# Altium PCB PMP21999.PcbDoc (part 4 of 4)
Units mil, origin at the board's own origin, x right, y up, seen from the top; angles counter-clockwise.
Board outline 7450 x 5800 mil, 6 copper layers (Top Layer, Signal Layer 3, Signal Layer 1, Signal Layer 2, Signal Layer 4, Bottom Layer), stack 66 mil thick; 237 components, 96 nets, 712 pads, 268 vias.
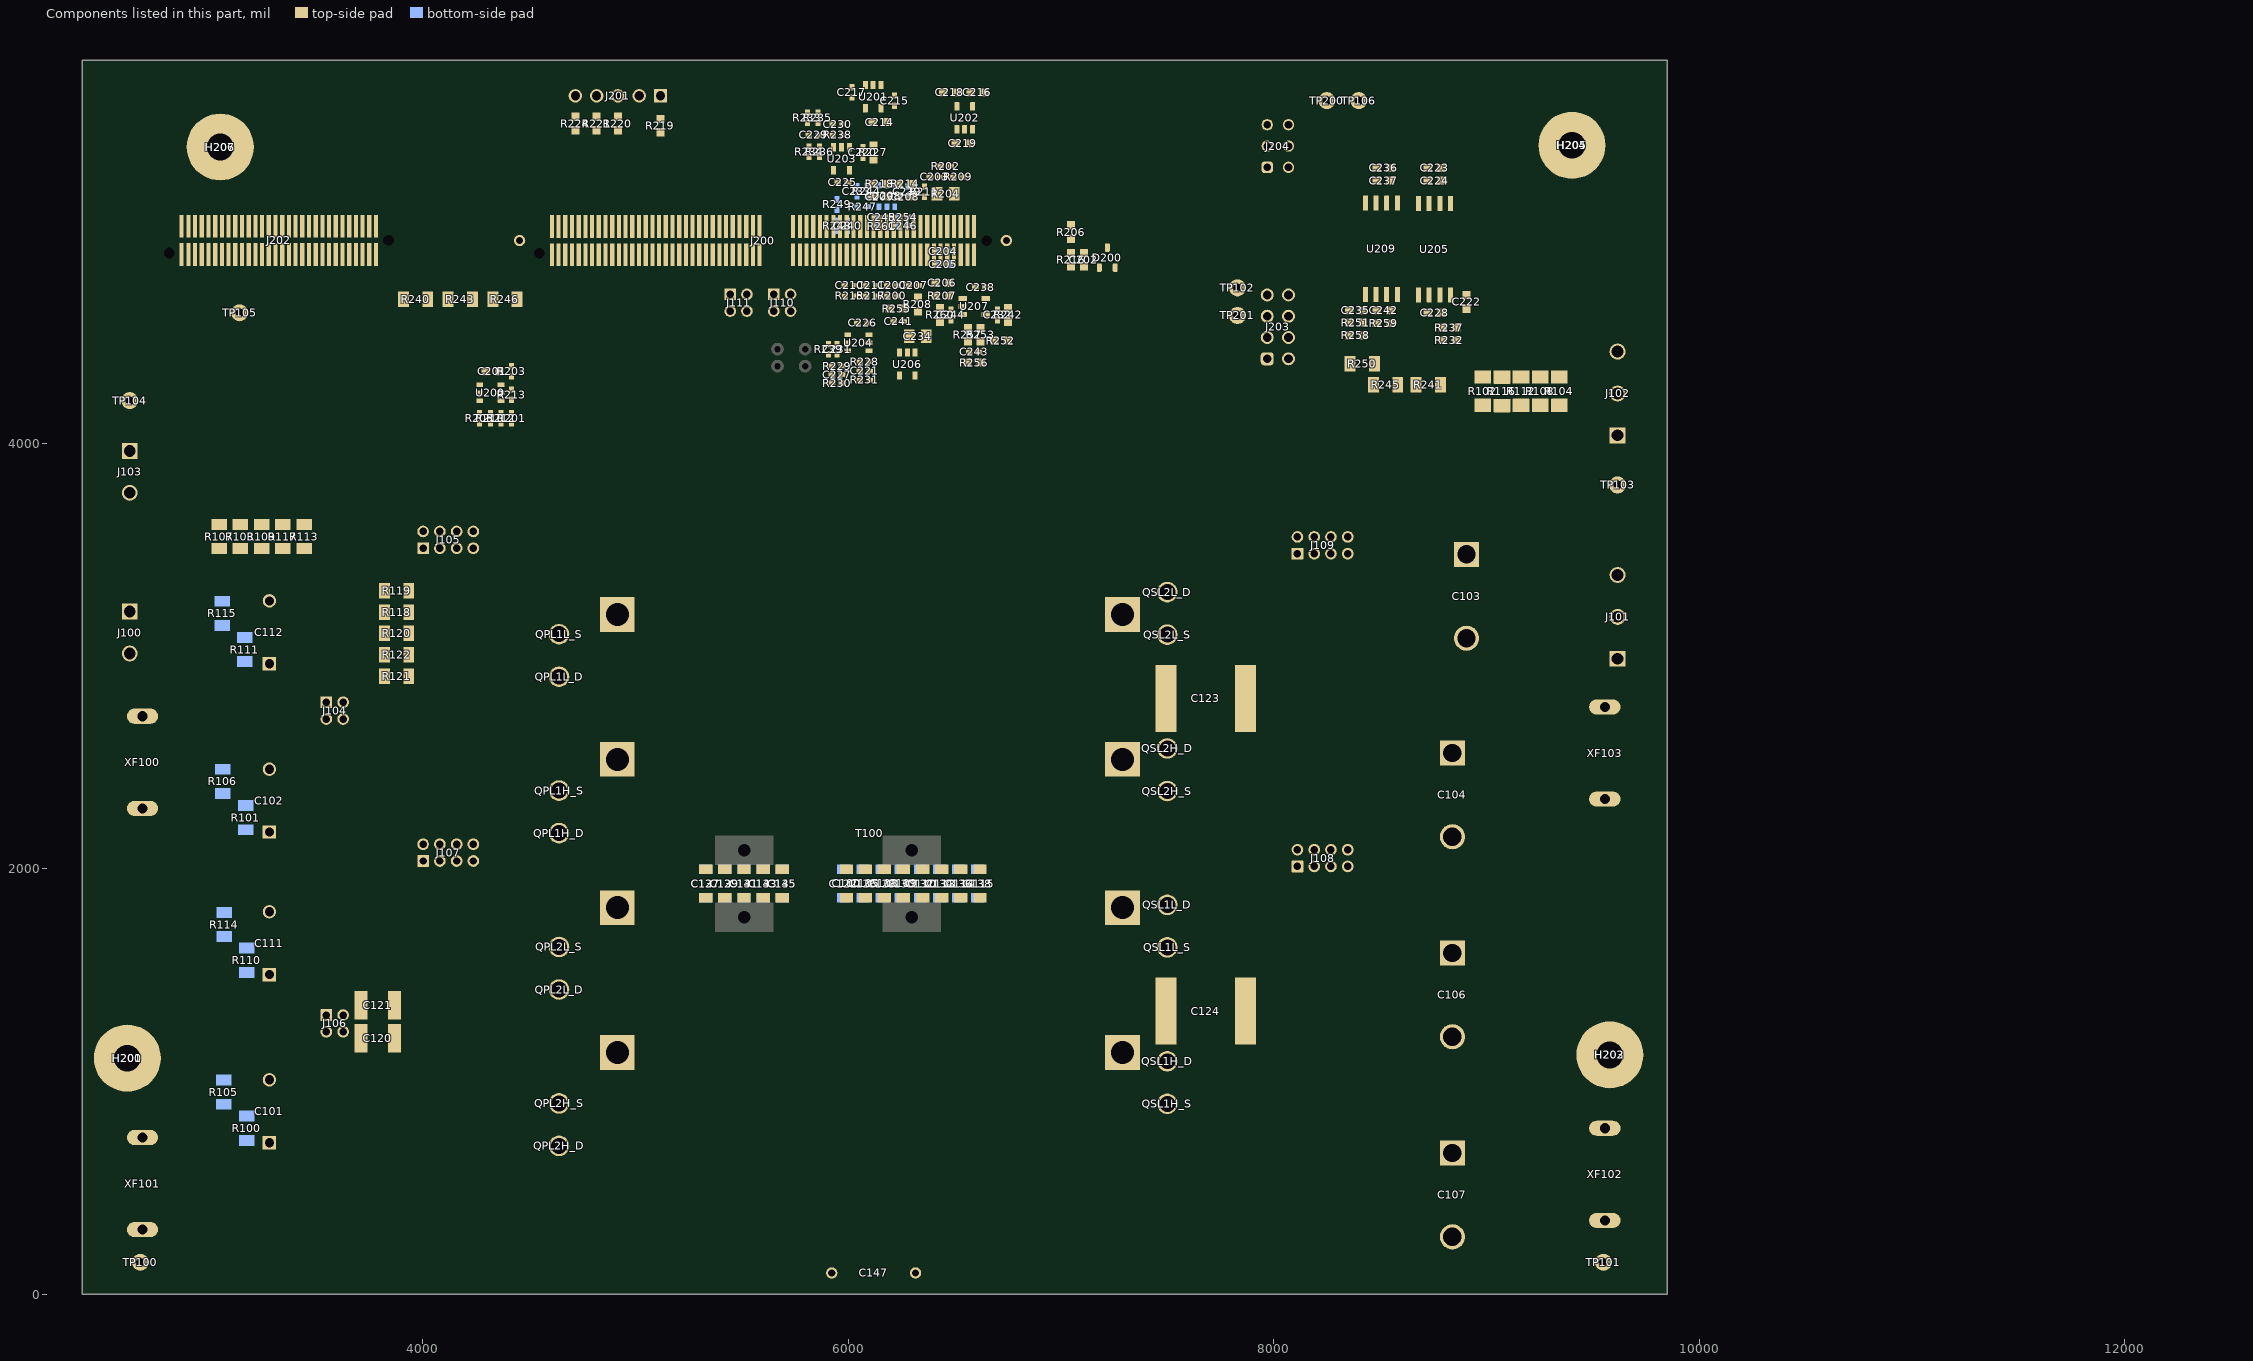
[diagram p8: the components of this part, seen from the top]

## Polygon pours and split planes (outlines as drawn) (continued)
VBUS on Signal Layer 4 "VBUS" (solid, pour order 274): 2510,3270 2490,3250 2490,2240 2510,2220 2840,2220 2860,2240 2860,3250 2840,3270
BATT_RTN on Signal Layer 4 "BATT_RTN" (solid, pour order 430): 8929.94,4280 8916.4,4293.54 8916.4,4453.54 9026.4,4563.54 9786.4,4563.54 9806.4,4543.54 9806.4,3926.4 9640,3760 9590,3760 9426.4,3923.6 9426.4,4223.54 9369.94,4280
VBATT on Signal Layer 4 "VBATT" (solid, pour order 442): 9636.4,2233.54 9686.4,2283.54 9686.4,3443.54 9656.4,3473.54 9536.4,3473.54 9376.4,3313.54 9376.4,2283.54 9426.4,2233.54
SGND on Signal Layer 4 "SGND" (solid, pour order 478): 39 vertices, not listed, extent 7438.19,1340 8480,4160
HVBUS on Signal Layer 4 "HVBUS" (solid, pour order 496): 36 vertices, not listed, extent 2580,80 4700,2240
SGND on Signal Layer 4 "SGND" (solid, pour order 518): 33 vertices, not listed, extent 6290,10 9410,4210
RTN on Signal Layer 4 "RTN" (solid, pour order 522): 2580,4260 2560,4240 2560,3740 2702.64,3597.36 3476.26,3597.36 3497.49,3618.59 3497.49,4039.53 3277.02,4260
PGND on Signal Layer 4 "PGND" (solid, pour order 532): 27 vertices, not listed, extent 2560,3381.39 9830,5791
SGND on Signal Layer 4 "SGND" (solid, pour order 542): 19 vertices, not listed, extent 7670,4169.11 9030,4807.01
no net on Bottom Layer "LEG_2_SEC" (solid, pour order 416): 17 vertices, not listed, extent 7100,2300 7560,3390
Leg_2_Sec on Bottom Layer "LEG_2_SEC" (solid, pour order 410): 17 vertices, not listed, extent 7100,2300 7560,3390
Leg_1_Sec on Bottom Layer "LEG_1_SEC" (solid, pour order 398): 17 vertices, not listed, extent 7100,780 7560,1930
VOUT on Bottom Layer "Vout" (solid, pour order 392): 35 vertices, not listed, extent 7440,100 9680,3570
PGND on Bottom Layer "PGND" (solid, pour order 390): 20 vertices, not listed, extent 2920,1100 3840,3530
Crs_1 on Bottom Layer "Crs_1" (solid, pour order 356): 5951.81,1890 5931.81,1870 5931.81,1730 5951.81,1710 6661.81,1710 6681.81,1730 6681.81,1870 6661.81,1890
NetC100_2 on Bottom Layer "C100_2" (solid, pour order 342): 5950,2150.16 5930,2130.16 5930,1980 5950.39,1959.61 6659.61,1959.61 6680,1980 6680,2130 6660,2150
NetC102_2 on Bottom Layer "C102_2" (solid, pour order 332): 2983.46,2463.86 2983.46,2883.86 3103.46,3003.86 3323.46,3003.86 3343.46,2983.86 3343.46,2443.86 3323.46,2423.86 3253.46,2423.86 3233.46,2443.86 3003.46,2443.86
NetC101_2 on Bottom Layer "C101_2" (solid, pour order 318): 2970,1000 2970,1420 3090,1540 3310,1540 3330,1520 3330,980 3310,960 3240,960 3220,980 2990,980
HVBUS on Bottom Layer "HVBUS" (solid, pour order 284): 34 vertices, not listed, extent 2580,80 4700,2240
Leg_1_Prim on Bottom Layer "Leg_1_Prim" (solid, pour order 300): 4840,3300 4820,3280 4820,3101.26 4678.74,2960 4600,2960 4580,2940 4580,2330 4600,2310 4890,2310 5010,2430 5010,3280 4990,3300
Leg_2_Prim on Bottom Layer "Leg_2_Prim" (solid, pour order 296): 4613.42,1480 4593.42,1460 4593.42,860 4613.42,840 4813.42,840 5023.42,1050 5023.42,1220 4763.42,1480
NetC127_1 on Bottom Layer "BOTTOM_LAYER_NETC127_1_P254" (solid, remove dead copper, pour order 254): 5180,1940 5150,1970 5150,2139.44 5170.56,2160 5850,2160 5870,2140 5870,1970 5840,1940
Crp_1 on Bottom Layer "BOTTOM_LAYER_CRP_1_P260" (solid, remove dead copper, pour order 260): 5180,1890 5150,1860 5150,1730 5180,1700 5830,1700 5860,1730 5860,1870 5840,1890
VBUS on Bottom Layer "VBUS" (solid, pour order 272): 2510,3270 2490,3250 2490,2240 2510,2220 2840,2220 2860,2240 2860,3250 2840,3270
BATT_RTN on Bottom Layer "BATT_RTN" (solid, pour order 432): 8929.94,4280 8916.4,4293.54 8916.4,4453.54 9026.4,4563.54 9786.4,4563.54 9806.4,4543.54 9806.4,3926.4 9640,3760 9590,3760 9426.4,3923.6 9426.4,4223.54 9369.94,4280
VBATT on Bottom Layer "VBATT" (solid, pour order 450): 9636.4,2233.54 9686.4,2283.54 9686.4,3443.54 9656.4,3473.54 9536.4,3473.54 9376.4,3313.54 9376.4,2283.54 9426.4,2233.54
SGND on Bottom Layer "SGND" (solid, pour order 482): 21 vertices, not listed, extent 7660,1110 9410,4210
SGND on Bottom Layer "SGND" (solid, pour order 480): 28 vertices, not listed, extent 7440,3031.26 8480,4160
no net on Bottom Layer "HVBUS" (solid, pour order 490): 34 vertices, not listed, extent 2580,80 4700,2240
CS on Bottom Layer "CS" (solid, pour order 506): 17 vertices, not listed, extent 3900,1570 4710,3390
RTN on Bottom Layer "RTN" (solid, pour order 520): 2580,4260 2560,4240 2560,3740 2700,3600 3479.74,3600 3497.49,3617.75 3497.49,4039.53 3277.02,4260
PGND on Bottom Layer "PGND" (solid, pour order 530): 33 vertices, not listed, extent 2560,3360 9830,5791
SGND on Bottom Layer "SGND" (solid, pour order 540): 23 vertices, not listed, extent 7670,4141.13 9030,4807.01

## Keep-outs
Keep-Out Layer:
  text ".Layer_Name" at 577,-858.49 h60

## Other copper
Top Layer:
  text ".Layer_Name" at 577,-858.49 h60
Bottom Layer:
  text ".Layer_Name" at 577,-858.49 h60

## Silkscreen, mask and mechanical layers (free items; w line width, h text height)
Top Overlay:
  drawing of 153 lines, arcs and shapes, not listed
  text "5Vp" at 8170,5480 h72.83
  text "PGND" at 8370,5480 h72.83
  text "V1: 400V-600V DC / Power Max 7kW" at 2440,5115.5 h100 r270
  text "SGND" at 7616.01,4780 h72.83
  text "V2 / 250-450V DC / Pmax 6.6kW" at 9710,4670 h100 r90
  text "5Vs" at 7660,4627.86 h72.83
  text "-" at 9716.4,4623.54 h150
  text "Coil_Sec_N" at 4818,4550 h60
  text "Coil_Pri_N" at 4820,4450 h60
  text "PMP21999 RevA" at 2743.46,4394.47 h108.27
  text "Coil_Pri_P" at 4820,4350 h60
  text "Coil_Sec_P" at 4818,4231.87 h60
  text "-" at 2477.8,4109.68 h150
  text "+" at 9726.4,3513.58 h150
  text "+" at 2463.46,3330 h150
  text "Fuse F30AL650V / Installed between XF100 & XF101" at 2454.17,2172.36 h100 r270
  text "Crp" at 5170,2100 h30
  text "Crs" at 6008.16,2090 h30
  text "Board" at 5170,2040 h30
  text "Board" at 6008.79,2036.18 h30
  text "Fuse F30AL650V / Installed between XF102 & XF103" at 9808.81,1430 h100 r90
  text ".Layer_Name" at 577,-858.49 h60
  text "Fuse F30AL650V / Installed between XF100 & XF101" at 3950,-2600 h100 r270
  text "Fuse F30AL650V / Installed between XF100 & XF101" at -5650,-2780 h100 r270
Bottom Overlay:
  lines w10: 6338,5181.87 6378,5221.87 6718,5221.87 ; 6718,5111.87 6718,5431.87 6748,5461.87 7178,5461.87 7218,5421.87 7218,5121.87 7178,5081.87 6748,5081.87 6718,5111.87
  text ".Layer_Name" at 577,-858.49 h60
Top Paste:
  text ".Layer_Name" at 577,-858.49 h60
Bottom Paste:
  text ".Layer_Name" at 577,-858.49 h60
Top Solder:
  text ".Layer_Name" at 577,-858.49 h60
  text ".Layer_Name" at 577,-858.49 h60
Bottom Solder:
  text ".Layer_Name" at 577,-858.49 h60
Drill Guide:
  text ".Layer_Name" at 577,-858.49 h60
M1 Board Outline:
  the board outline again, w10
  text ".Layer_Name" at 577,-858.49 h60
M2 Board Dimensions:
  rectangle: 0,-275 125,-150
  rectangle: 125,-400 500,-275
  lines w7: 0,-275 1000,-275 ; 125,-400 125,-150 ; 250,-400 250,-150 ; 500,-400 500,-150 ; 750,-400 750,-150 ; 0,-400 1000,-400 1000,-150 0,-150 0,-400
  text ".Layer_Name" at 577,-858.49 h60
M3 3D STEP Top:
  text ".Layer_Name" at 577,-858.49 h60
M4 3D STEP Bottom:
  text ".Layer_Name" at 577,-858.49 h60
M5 Assembly Top:
  lines w10: -292,-930.17 6308,-930.17 ; -292,-726.83 6310,-726.83 ; -292,-523.5 -292,-1133.5 3713,-1133.5 6310,-1133.5 6310,-523.5 -291.5,-523.5 -291.5,-1133.5 1284,-1133.5 ; 2173,-1133.5 2173,-523.5 ; 3440,-726.83 3440,-523.5 ; 4280,-726.83 4280,-523.5 ; 4902,-1140 4902,-937.17
  text "COMPONENTS MARKED 'DNP' SHOULD NOT BE POPULATED." at 1153.5,-318.5 h60
  text "ASSEMBLY VARIANT:" at 1153,-434 h60
  text ".VariantName" at 2189,-434 h60
  text "PCB VIEWED FROM TOP SIDE" at -228.5,-655.67 h60
  text "BOARD #:" at 2248,-655.67 h60
  text ".PRJ_Number" at 2793.5,-655.67 h60
  text "REV:" at 3638,-655.67 h60
  text ".PCB_Rev" at 3929.5,-655.67 h60
  text "SVN REV:" at 4476,-655.67 h60
  text ".VersionControl_RevNumber" at 4982,-655.67 h60
  text "TID #:" at 2248,-859 h60
  text ".TID" at 2793.5,-859 h60
  text "PLOT NAME =" at -228.5,-1064.34 h60
  text ".plot_File_Name" at 577,-1064.34 h60
  text "GENERATED    :" at 2250,-1064.34 h60
  text ".Print_Date" at 3119.5,-1064.34 h60
  text ".Print_Time" at 3848.5,-1064.34 h60
  text "TEXAS INSTRUMENTS" at 5113,-1064.34 h60
M6 Assembly Bottom:
  lines w10: -292.5,-727.33 6309.5,-727.33 ; -290.5,-930.67 6309.5,-930.67 ; 1115.5,-1140.5 1115.5,-937.67 ; 1737.5,-727.33 1737.5,-524 ; 2577.5,-727.33 2577.5,-524 ; 3844.5,-1134 3844.5,-524 ; 4733.5,-1134 6309,-1134 6309,-524 -292.5,-524 -292.5,-1134 2304.5,-1134 6309.5,-1134 6309.5,-524
  text "COMPONENTS MARKED 'DNP' SHOULD NOT BE POPULATED." at 6102,-318 h60
  text ".VariantName" at 5058,-434 h60
  text "ASSEMBLY VARIANT:" at 6097,-434 h60
  text ".VersionControl_RevNumber" at 1035.5,-656.17 h60
  text "SVN REV:" at 1541.5,-656.17 h60
  text ".PCB_Rev" at 2088,-656.17 h60
  text "REV:" at 2379.5,-656.17 h60
  text ".PRJ_Number" at 3224,-656.17 h60
  text "BOARD #:" at 3769.5,-656.17 h60
  text "PCB VIEWED FROM BOTTOM SIDE" at 6246,-656.17 h60
  text ".TID" at 3224,-859.5 h60
  text "TID #:" at 3769.5,-859.5 h60
  text "TEXAS INSTRUMENTS" at 904.5,-1064.84 h60
  text ".Print_Time" at 2169,-1064.84 h60
  text ".Print_Date" at 2898,-1064.84 h60
  text "GENERATED    :" at 3767.5,-1064.84 h60
  text ".plot_File_Name" at 5440.5,-1064.84 h60
  text "PLOT NAME =" at 6246,-1064.84 h60
M9 Title Sheet:
  drawing of 57 lines, arcs and shapes, not listed
  text "1" at 739.84,8036.5 h70
  text "2" at 3235.5,8036.5 h70
  text "3" at 5724.84,8036.5 h70
  text "4" at 8231.51,8036.5 h70
  text "5" at 10730.5,8036.5 h70
  text "6" at 13235.5,8036.5 h70
  text "A" at -416.5,6893.5 h70
  text "A" at 14383.5,6893.5 h70
  text "B" at -416.5,4513.5 h70
  text "B" at 14383.5,4513.5 h70
  text "C" at -416.5,2138.5 h70
  text "C" at 14383.5,2138.5 h70
  text "PROJECT TITLE:" at 11343.5,277.5 h45
  text ".PRJ_Title" at 11393.5,144.17 h70
  text "DESIGNED FOR:" at 11343.5,-23.5 h45
  text ".PRJ_Customer" at 11393.5,-163.5 h70
  text "D" at -416.5,-231.5 h70
  text "D" at 14383.5,-231.5 h70
  text "FILE NAME:" at 11343.5,-323.5 h45
  text ".PCB_File_Name_No_Path" at 11393.5,-443.5 h70
  text "Texas Instruments (TI) and/or its licensors do not warrant the accuracy or completeness of this specification" at 6374,-605.34 h45
  text "ENGINEER:" at 11343.5,-613.5 h45
  text "LAYOUT BY:" at 12848.5,-613.5 h45
  text "or any information contained therein. TI and/or its licensors do not warrant that this design will meet" at 6329.01,-718 h45
  text ".PRJ_Engineer" at 11393.5,-768.49 h70
  text ".PCB_Layout" at 12899,-768.49 h70
  text "the specifications, will be suitable for your application or fit for any particular purpose, or will operate in" at 6329.01,-830.67 h45
  text ".Layer_Name" at 577,-858.49 h60
  text "ALTIUM DESIGNER VERSION:" at 12848.5,-923.5 h45
  text "an implementation. TI and/or its licensors do not warrant that the design is production worthy. You should" at 6329.01,-943.33 h45
  text "completely validate and test your design implementation to confirm the system functionality for your application." at 6374,-1056 h45
  text ".print_Scale" at 11393.5,-1056.83 h70
  text ".Application_BuildNumber" at 12899,-1056.83 h70
  text "1" at 739.84,-1263.5 h70
  text "2" at 3235.5,-1263.5 h70
  text "3" at 5724.84,-1263.5 h70
  text "4" at 8231.51,-1263.5 h70
  text "5" at 10730.5,-1263.5 h70
  text "6" at 13235.5,-1263.5 h70
M10 Fab Notes:
  drawing of 189 lines, arcs and shapes, not listed
  text "DESIGN INFORMATION" at 12382.02,6356.17 h60
  text "MIN. TRACK WIDTH:" at 11737.46,6224.05 h60
  text "8" at 12833.7,6224.05 h60
  text "MIL" at 12988.46,6224.05 h60
  text "MIN. CLEARANCE:" at 11737.46,6099.92 h60
  text "0.2" at 12773.7,6099.93 h60
  text "mm" at 12988.46,6099.92 h60
  text "MIN. VIA PAD SIZE:" at 11737.46,5975.8 h60
  text "20" at 12803.71,5975.8 h60
  text "MIL" at 12988.46,5975.8 h60
  text "0.05mm (2MIL)" at 12432.46,5845.9 h60
  text "MINIMUM ANNULAR RING" at 11408.23,5837.67 h60
  text "EXTERNAL" at 13140.46,5837.67 h60
  text "PER" at 11608.23,5727.55 h60
  text "IPC-D-275 CLASS 2 LEVEL C" at 11828.23,5727.54 h60
  text "MIL, HOLES" at 13316.46,5627.07 h60
  text "+/-" at 12924,5618.48 h60
  text "+/-" at 13778,5618.48 h60
  text "REGISTRATION TOLERANCES:" at 11408.23,5617.42 h60
  text "METAL" at 12608,5617.42 h60
  text "5" at 13184.2,5617.42 h60
  text "3" at 14017.2,5617.42 h60
  text "MIL" at 14133.46,5617.42 h60
  text "HOLE SIZE TOLERANCE (UNLESS OTHERWISE SPECIFIED):" at 11408.23,5519.1 h60
  text "+/-" at 13778,5516.23 h60
  text "3" at 14017.2,5515.17 h60
  text "MIL" at 14133.46,5515.17 h60
  text "MATERIAL:" at 11333.46,5377.52 h60
  text "FR-4 High Tg" at 12319.9,5249 h60
  text "X" at 12175.46,5241.01 h60
  text "FR-408" at 11754.46,5236.49 h60
  text "OTHER" at 13242.46,5236.49 h60
  text "62 MIL (1.6mm) +/-10%" at 12074.56,5093.46 h60
  text "X" at 11954.46,5091.01 h60
  text "THICKNESS:" at 11408.23,5085.24 h60
  text "OTHER" at 13359.46,5085.24 h60
  text "TOLERANCE:" at 11408.23,4946.92 h60
  text "X" at 12256.46,4946.92 h60
  text "ANSI IPC-6012 TYPE 3 CLASS 2" at 12434.48,4946.92 h60
  text "OTHER +/-" at 12434.46,4802.73 h60
  text "BOW & TWIST:" at 11408.23,4657.54 h60
  text "X" at 12256.46,4657.54 h60
  text "ANSI IPC-6012 TYPE 3 CLASS 2" at 12434.48,4657.54 h60
  text "OTHER +/-" at 12434.46,4510.85 h60
  text "DRILLING:" at 11333.46,4380.23 h60
  text "NC_DRILL FILES" at 13094.46,4275.04 h60
  text "REFERENCE:" at 11408.23,4271.1 h60
  text "X" at 12065.46,4271.01 h60
  text "AS SHOWN" at 12243.46,4271.1 h60
  text "X" at 12966.46,4271.1 h60
  text "OTHER" at 13392.46,4128.85 h60
  text "PTH COPPER THICKNESS:" at 11407.91,4125.32 h60
  text "X" at 12547.14,4125.32 h60
  text "20-30 um" at 12675.14,4125.32 h60
  text "BOARD FINISH:" at 11333.46,3977.73 h60
  text "SILKSCREEN:" at 11488.68,3867.6 h60
  text "X" at 12446.46,3867.6 h60
  text "TOP" at 12563.46,3867.6 h60
  text "X" at 12956.46,3867.6 h60
  text "BOTTOM" at 13074.46,3867.6 h60
  text "SILKSCREEN COLOR:" at 11488.68,3712.41 h60
  text "X" at 12445.46,3712.41 h60
  text "WHITE" at 12563.46,3712.41 h60
  text "OTHER" at 13074.46,3712.41 h60
  text "X" at 12576.46,3568.96 h60
  text "GREEN" at 12694.46,3568.96 h60
  text "OTHER" at 13312.46,3568.96 h60
  text "SOLDER RESIST COLOR:" at 11488.68,3562.1 h60
  text "X" at 12576.46,3414.71 h60
  text "MATTE" at 12694.46,3414.71 h60
  text "SEMI-GLOSS" at 13312,3414.07 h60
  text "IMMERSION GOLD (ENIG)" at 12394.46,3241.94 h60
  text "ENEPIG" at 13732,3234.72 h60
  text "SURFACE FINISH:" at 11333.46,3233.72 h60
  text "X" at 12216.46,3233.72 h60
  text "IMM. TIN/SILVER OR EQUIV" at 11663,3096.4 h60
  text "OTHER" at 13094.46,3092.47 h60
  text "ARRAY/PANEL:" at 11333.46,2937.09 h60
  text "CUT AND TRIM PER M1 BOARD OUTLINE" at 12394.46,2928.87 h60
  text "N.C. ROUTE" at 12394.46,2792.9 h60
  text "X" at 13082.46,2792.9 h60
  text "V. SCORE" at 13260.46,2792.9 h60
  text "CERTIFICATION:" at 11333.46,2663.77 h60
  text "MATERIALS AND WORKMANSHIP FOR ALL PCBS" at 12058.46,2663.77 h60
  text "TO MEET OR EXCEED THE REQUIREMENTS OF:" at 12058.46,2569.71 h60
  text "X" at 11695.97,2441.08 h60
  text "ANSI IPC-A-600F CLASS ->" at 11823.96,2441.08 h60
  text "X" at 13471.97,2441.08 h60
  text "2" at 13581.96,2441.08 h60
  text "1" at 13266.96,2439.58 h60
  text "3" at 13935.96,2439.58 h60
  text "X" at 12507.97,2293.39 h60
  text "RoHS" at 12635.96,2293.39 h60
  text "OTHER" at 13280.36,2293.39 h60
  text "PER ORDER" at 13677.42,2293.39 h60
  text "ALL BOARDS MUST MEET OR EXCEED UL94-V0 REQUIREMENTS." at 11361,2139.57 h60
  text "PCB MUST BEAR THE UL94V-0 UL REGISTERED MATERIAL ID NUMBER" at 11361,2023.5 h60
  text "ADDITIONAL REQUIREMENTS:" at 11333.46,1854.08 h60
  text "MICROSECTION:" at 11408.23,1746.95 h60
  text "YES" at 12313.96,1746.95 h60
  text "REQUIRED" at 13175.46,1602.62 h60
  text "BARE BOARD ELEC. TEST:" at 11408.23,1599.76 h60
  text "NONE" at 12713.96,1599.76 h60
  text "X" at 13057.46,1599.76 h60
  text "PER ORDER" at 13767.46,1599.76 h60
  text "XX MIL VIAS REQUIRE NON-CONDUCTIVE FILL AND PLANARIZE" at 11576.38,1394.82 h59
  text "XX MIL VIAS REQUIRE CONDUCTIVE FILL AND PLANARIZE" at 11584.38,1290.84 h60
  text "OUTER XX MIL TRACES REQUIRE 50 OHM SINGLE-ENDED IMPEDANCE" at 11583.39,1127.46 h58
  text "LAYER 2 & 3 (INNER LAYERS) XX MIL WIDE, XX MIL SPACE / TRACES REQUIRE 100 OHM DIFFERENTIAL IMPEDANCE" at 11575.39,891.74 h60
  text ".Layer_Name" at 577,-858.49 h60
M11 Gerber Information:
  lines w10: -292,-930.17 6308,-930.17 ; -292,-726.83 6310,-726.83 ; -292,-523.5 -292,-1133.5 3713,-1133.5 6310,-1133.5 6310,-523.5 -291.5,-523.5 -291.5,-1133.5 1284,-1133.5 ; 2173,-1133.5 2173,-523.5 ; 3440,-726.83 3440,-523.5 ; 4280,-726.83 4280,-523.5 ; 4902,-1140 4902,-937.17
  text "ALL ARTWORK VIEWED FROM TOP SIDE" at -228.5,-655.67 h60
  text "BOARD #:" at 2248,-655.67 h60
  text ".PRJ_Number" at 2793.5,-655.67 h60
  text "REV:" at 3638,-655.67 h60
  text ".PCB_Rev" at 3929.5,-655.67 h60
  text "SVN REV:" at 4476,-655.67 h60
  text ".VersionControl_RevNumber" at 4982,-655.67 h60
  text "LAYER NAME =" at -228.5,-858.49 h60
  text "TID #:" at 2248,-859 h60
  text ".TID" at 2793.5,-859 h60
  text "PLOT NAME =" at -228.5,-1064.34 h60
  text ".plot_File_Name" at 577,-1064.34 h60
  text "GENERATED    :" at 2250,-1064.34 h60
  text ".Print_Date" at 3119.5,-1064.34 h60
  text ".Print_Time" at 3848.5,-1064.34 h60
  text "TEXAS INSTRUMENTS" at 5113,-1064.34 h60
M12 Stackup:
  drawing of 399 lines, arcs and shapes, not listed
  text "Layer" at 6700,7770 h60
  text "Name" at 7109.91,7770 h60
  text "Material" at 8049.65,7770 h60
  text "Thickness" at 8909.42,7770 h60
  text "Constant" at 9559.26,7770 h60
  text "Board Layer Stack" at 10129.12,7770 h60
  text "1" at 6700,7650 h60
  text "Top Overlay" at 7109.91,7650 h60
  text "2" at 6700,7530 h60
  text "Top Solder" at 7109.91,7530 h60
  text "Solder Resist" at 8049.65,7530 h60
  text "0.40mil" at 8909.42,7530 h60
  text "3.5" at 9559.26,7530 h60
  text "3" at 6700,7410 h60
  text "Top Layer" at 7109.91,7410 h60
  text "Copper" at 8049.65,7410 h60
  text "4.20mil" at 8909.42,7410 h60
  text "4" at 6700,7290 h60
  text "Dielectric1" at 7109.91,7290 h60
  text "8.00mil" at 8909.42,7290 h60
  text "4.2" at 9559.26,7290 h60
  text "5" at 6700,7170 h60
  text "Signal Layer 3" at 7109.91,7170 h60
  text "Copper" at 8049.65,7170 h60
  text "1.40mil" at 8909.42,7170 h60
  text "6" at 6700,7050 h60
  text "Dielectric 4" at 7109.91,7050 h60
  text "FR-4" at 8049.65,7050 h60
  text "14.00mil" at 8909.42,7050 h60
  text "4.2" at 9559.26,7050 h60
  text "7" at 6700,6930 h60
  text "Signal Layer 1" at 7109.91,6930 h60
  text "Copper" at 8049.65,6930 h60
  text "1.40mil" at 8909.42,6930 h60
  text "8" at 6700,6810 h60
  text "Dielectric 2" at 7109.91,6810 h60
  text "8.00mil" at 8909.42,6810 h60
  text "4.2" at 9559.26,6810 h60
  text "9" at 6700,6690 h60
  text "Signal Layer 2" at 7109.91,6690 h60
  text "Copper" at 8049.65,6690 h60
  text "1.40mil" at 8909.42,6690 h60
  text "10" at 6700,6570 h60
  text "Dielectric 5" at 7109.91,6570 h60
  text "FR-4" at 8049.65,6570 h60
  text "14.00mil" at 8909.42,6570 h60
  text "4.2" at 9559.26,6570 h60
  text "11" at 6700,6450 h60
  text "Signal Layer 4" at 7109.91,6450 h60
  text "Copper" at 8049.65,6450 h60
  text "1.40mil" at 8909.42,6450 h60
  text "12" at 6700,6330 h60
  text "Dielectric 3" at 7109.91,6330 h60
  text "8.00mil" at 8909.42,6330 h60
  text "4.2" at 9559.26,6330 h60
  text "13" at 6700,6210 h60
  text "Bottom Layer" at 7109.91,6210 h60
  text "Copper" at 8049.65,6210 h60
  text "4.20mil" at 8909.42,6210 h60
  text "14" at 6700,6090 h60
  text "Bottom Solder" at 7109.91,6090 h60
  text "Solder Resist" at 8049.65,6090 h60
  text "0.40mil" at 8909.42,6090 h60
  text "3.5" at 9559.26,6090 h60
  text "15" at 6700,5970 h60
  text "Bottom Overlay" at 7109.91,5970 h60
  text ".Layer_Name" at 577,-858.49 h60
M13 Component Bodies Top:
  text ".Layer_Name" at 577,-858.49 h60
M14 Component Bodies Bottom:
  text ".Layer_Name" at 577,-858.49 h60
M15 Courtyards Top:
  text ".Layer_Name" at 577,-858.49 h60
M16 Courtyards Bottom:
  text ".Layer_Name" at 577,-858.49 h60
Drill Drawing:
  drawing of 175 lines, arcs and shapes, not listed
  text "Symbol" at 600.63,7884.76 h49.98
  text "Count" at 961.6,7884.76 h49.98
  text "Hole Size" at 1377.2,7884.76 h49.98
  text "Plated" at 2181.44,7884.76 h49.98
  text "Hole Type" at 2542.42,7884.76 h49.98
  text "Drill Layer Pair" at 3061.63,7884.76 h49.98
  text "Via/Pad" at 4108.77,7884.76 h49.98
  text "Pad Shape" at 4528.04,7884.76 h49.98
  text "Template" at 5055.58,7884.76 h49.98
  text "Description" at 5936.16,7884.76 h49.98
  text "Hole Tolerance (+)" at 6538.64,7884.76 h49.98
  text "Hole Tolerance (-)" at 7474.25,7884.76 h49.98
  text "Hole Length" at 8409.86,7884.76 h49.98
  text "Routed Path Length" at 9193.28,7884.76 h49.98
  text "2" at 961.6,7780.63 h41.65
  text "33.07mil (0.840mm)" at 1377.2,7780.63 h41.65
  text "PTH" at 2181.44,7780.63 h41.65
  text "Round" at 2542.42,7780.63 h41.65
  text "Top Layer - Bottom Layer" at 3061.63,7780.63 h41.65
  text "Pad" at 4108.77,7780.63 h41.65
  text "Rounded" at 4528.04,7780.63 h41.65
  text "c135h84" at 5055.58,7780.63 h41.65
  text "-" at 8409.86,7780.63 h41.65
  text "-" at 9193.28,7780.63 h41.65
  text "2" at 961.6,7676.49 h41.65
  text "33.47mil (0.850mm)" at 1377.2,7676.49 h41.65
  text "PTH" at 2181.44,7676.49 h41.65
  text "Round" at 2542.42,7676.49 h41.65
  text "Top Layer - Bottom Layer" at 3061.63,7676.49 h41.65
  text "Pad" at 4108.77,7676.49 h41.65
  text "Rounded" at 4528.04,7676.49 h41.65
  text "c135h85" at 5055.58,7676.49 h41.65
  text "-" at 8409.86,7676.49 h41.65
  text "-" at 9193.28,7676.49 h41.65
  text "4" at 961.6,7572.36 h41.65
  text "30.00mil (0.762mm)" at 1377.2,7572.36 h41.65
  text "PTH" at 2181.44,7572.36 h41.65
  text "Round" at 2542.42,7572.36 h41.65
  text "Top Layer - Bottom Layer" at 3061.63,7572.36 h41.65
  text "Pad" at 4108.77,7572.36 h41.65
  text "Rounded" at 4528.04,7572.36 h41.65
  text "c152h76" at 5055.58,7572.36 h41.65
  text "-" at 8409.86,7572.36 h41.65
  text "-" at 9193.28,7572.36 h41.65
  text "C" at 578.33,7562.37 h46.28
  text "4" at 961.6,7468.22 h41.65
  text "50.00mil (1.270mm)" at 1377.2,7468.22 h41.65
  text "NPTH" at 2181.44,7468.22 h41.65
  text "Round" at 2542.42,7468.22 h41.65
  text "Top Layer - Bottom Layer" at 3061.63,7468.22 h41.65
  text "Pad" at 4108.77,7468.22 h41.65
  text "Rounded" at 4528.04,7468.22 h41.65
  text "c3hn127m90" at 5055.58,7468.22 h41.65
  text "-" at 8409.86,7468.22 h41.65
  text "-" at 9193.28,7468.22 h41.65
  text "4" at 961.6,7364.09 h41.65
  text "59.06mil (1.500mm)" at 1377.2,7364.09 h41.65
  text "PTH" at 2181.44,7364.09 h41.65
  text "Rectangle" at 2542.42,7364.09 h41.65
  text "Top Layer - Bottom Layer" at 3061.63,7364.09 h41.65
  text "Pad" at 4108.77,7364.09 h41.65
  text "Rectangle" at 4528.04,7364.09 h41.65
  text "r700_350h150_300" at 5055.58,7364.09 h41.65
  text "118.11mil (3.000mm)" at 8409.86,7364.09 h41.65
  text "118.11mil (3.000mm)" at 9193.28,7364.09 h41.65
  text "4" at 961.6,7259.96 h41.65
  text "125.98mil (3.200mm)" at 1377.2,7259.96 h41.65
  text "PTH" at 2181.44,7259.96 h41.65
  text "Round" at 2542.42,7259.96 h41.65
  text "Top Layer - Bottom Layer" at 3061.63,7259.96 h41.65
  text "Pad" at 4108.77,7259.96 h41.65
  text "Rounded" at 4528.04,7259.96 h41.65
  text "c800h320" at 5055.58,7259.96 h41.65
  text "-" at 8409.86,7259.96 h41.65
  text "-" at 9193.28,7259.96 h41.65
  text "B" at 578.33,7249.96 h46.28
  text "6" at 961.6,7155.82 h41.65
  text "35.43mil (0.900mm)" at 1377.2,7155.82 h41.65
  text "PTH" at 2181.44,7155.82 h41.65
  text "Round" at 2542.42,7155.82 h41.65
  text "Top Layer - Bottom Layer" at 3061.63,7155.82 h41.65
  text "Pad" at 4108.77,7155.82 h41.65
  text "(Mixed)" at 4528.04,7155.82 h41.65
  text "(Mixed)" at 5055.58,7155.82 h41.65
  text "3.15mil (0.080mm)" at 6538.64,7155.82 h41.65
  text "3.15mil (0.080mm)" at 7474.25,7155.82 h41.65
  text "-" at 8409.86,7155.82 h41.65
  text "-" at 9193.28,7155.82 h41.65
  text "7" at 961.6,7051.69 h41.65
  text "108.27mil (2.750mm)" at 1377.2,7051.69 h41.65
  text "PTH" at 2181.44,7051.69 h41.65
  text "Square" at 2542.42,7051.69 h41.65
  text "Top Layer - Bottom Layer" at 3061.63,7051.69 h41.65
  text "Pad" at 4108.77,7051.69 h41.65
  text "Rectangle" at 4528.04,7051.69 h41.65
  text "s415h275m415p100415" at 5055.58,7051.69 h41.65
  text "-" at 8409.86,7051.69 h41.65
  text "-" at 9193.28,7051.69 h41.65
  text "8" at 961.6,6947.56 h41.65
  text "40.95mil (1.040mm)" at 1377.2,6947.56 h41.65
  text "PTH" at 2181.44,6947.56 h41.65
  text "Round" at 2542.42,6947.56 h41.65
  text "Top Layer - Bottom Layer" at 3061.63,6947.56 h41.65
  text "Pad" at 4108.77,6947.56 h41.65
  text "(Mixed)" at 4528.04,6947.56 h41.65
  text "(Mixed)" at 5055.58,6947.56 h41.65
  text "-" at 8409.86,6947.56 h41.65
  text "-" at 9193.28,6947.56 h41.65
  text "A" at 578.33,6937.56 h46.28
  text "8" at 961.6,6843.42 h41.65
  text "47.24mil (1.200mm)" at 1377.2,6843.42 h41.65
  text "PTH" at 2181.44,6843.42 h41.65
  text "Slot" at 2542.42,6843.42 h41.65
  text "Top Layer - Bottom Layer" at 3061.63,6843.42 h41.65
  text "Pad" at 4108.77,6843.42 h41.65
  text "Rounded" at 4528.04,6843.42 h41.65
  text "r180_375h120_250r100" at 5055.58,6843.42 h41.65
  text "98.43mil (2.500mm)" at 8409.86,6843.42 h41.65
  text "51.18mil (1.300mm)" at 9193.28,6843.42 h41.65
  text "8" at 961.6,6739.29 h41.65
  text "86.61mil (2.200mm)" at 1377.2,6739.29 h41.65
  text "PTH" at 2181.44,6739.29 h41.65
  text "Round" at 2542.42,6739.29 h41.65
  text "Top Layer - Bottom Layer" at 3061.63,6739.29 h41.65
  text "Pad" at 4108.77,6739.29 h41.65
  text "(Mixed)" at 4528.04,6739.29 h41.65
  text "(Mixed)" at 5055.58,6739.29 h41.65
  text "-" at 8409.86,6739.29 h41.65
  text "-" at 9193.28,6739.29 h41.65
  text "9" at 961.6,6635.15 h41.65
  text "40.00mil (1.016mm)" at 1377.2,6635.15 h41.65
  text "PTH" at 2181.44,6635.15 h41.65
  text "Round" at 2542.42,6635.15 h41.65
  text "Top Layer - Bottom Layer" at 3061.63,6635.15 h41.65
  text "Pad" at 4108.77,6635.15 h41.65
  text "Rounded" at 4528.04,6635.15 h41.65
  text "c203h102" at 5055.58,6635.15 h41.65
  text "-" at 8409.86,6635.15 h41.65
  text "-" at 9193.28,6635.15 h41.65
  text "10" at 961.6,6531.02 h41.65
  text "55.12mil (1.400mm)" at 1377.2,6531.02 h41.65
  text "PTH" at 2181.44,6531.02 h41.65
  text "Round" at 2542.42,6531.02 h41.65
  text "Top Layer - Bottom Layer" at 3061.63,6531.02 h41.65
  text "Pad" at 4108.77,6531.02 h41.65
  text "(Mixed)" at 4528.04,6531.02 h41.65
  text "(Mixed)" at 5055.58,6531.02 h41.65
  text "-" at 8409.86,6531.02 h41.65
  text "-" at 9193.28,6531.02 h41.65
  text "13" at 961.6,6426.89 h41.65
  text "43.31mil (1.100mm)" at 1377.2,6426.89 h41.65
  text "PTH" at 2181.44,6426.89 h41.65
  text "Round" at 2542.42,6426.89 h41.65
  text "Top Layer - Bottom Layer" at 3061.63,6426.89 h41.65
  text "Pad" at 4108.77,6426.89 h41.65
  text "(Mixed)" at 4528.04,6426.89 h41.65
  text "(Mixed)" at 5055.58,6426.89 h41.65
  text "-" at 8409.86,6426.89 h41.65
  text "-" at 9193.28,6426.89 h41.65
  text "16" at 961.6,6322.75 h41.65
  text "75.00mil (1.905mm)" at 1377.2,6322.75 h41.65
  text "PTH" at 2181.44,6322.75 h41.65
  text "Round" at 2542.42,6322.75 h41.65
  text "Top Layer - Bottom Layer" at 3061.63,6322.75 h41.65
  text "Pad" at 4108.77,6322.75 h41.65
  text "Rounded" at 4528.04,6322.75 h41.65
  text "c245h190" at 5055.58,6322.75 h41.65
  text "-" at 8409.86,6322.75 h41.65
  text "-" at 9193.28,6322.75 h41.65
  text "48" at 961.6,6218.62 h41.65
  text "35.04mil (0.890mm)" at 1377.2,6218.62 h41.65
  text "PTH" at 2181.44,6218.62 h41.65
  text "Round" at 2542.42,6218.62 h41.65
  text "Top Layer - Bottom Layer" at 3061.63,6218.62 h41.65
  text "Pad" at 4108.77,6218.62 h41.65
  text "(Mixed)" at 4528.04,6218.62 h41.65
  text "(Mixed)" at 5055.58,6218.62 h41.65
  text "-" at 8409.86,6218.62 h41.65
  text "-" at 9193.28,6218.62 h41.65
  text "268" at 961.6,6114.49 h41.65
  text "10.00mil (0.254mm)" at 1377.2,6114.49 h41.65
  text "PTH" at 2181.44,6114.49 h41.65
  text "Round" at 2542.42,6114.49 h41.65
  text "Top Layer - Bottom Layer" at 3061.63,6114.49 h41.65
  text "Via" at 4108.77,6114.49 h41.65
  text "Rounded" at 4528.04,6114.49 h41.65
  text "v51h25" at 5055.58,6114.49 h41.65
  text "-" at 8409.86,6114.49 h41.65
  text "-" at 9193.28,6114.49 h41.65
  text "421 Total" at 961.6,6010.35 h41.65
  text "Slot definitions :" at 600.63,5903.59 h41.65
  text "Routed Path Length" at 1326.11,5903.59 h41.65
  text "= Calculated from tool start centre position to tool end centre position." at 2100.17,5903.59 h41.65
  text "Hole Length" at 1326.11,5828.07 h41.65
  text "= Routed Path Length + Tool Size = Slot length as defined in the PCB layout" at 1815.63,5828.07 h41.65
  text ".Layer_Name" at 577,-858.49 h60
M17 Embedded Cavity:
  text ".Layer_Name" at 577,-858.49 h60
M18 Embedded Assembly:
  text ".Layer_Name" at 577,-858.49 h60
M19 Embedded Keepout:
  text ".Layer_Name" at 577,-858.49 h60

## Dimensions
2400,0 to 2400,5800 on M2 Board Dimensions
2400,0 to 9850,0 on M2 Board Dimensions
0,-400 to 1000,-400 on M2 Board Dimensions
